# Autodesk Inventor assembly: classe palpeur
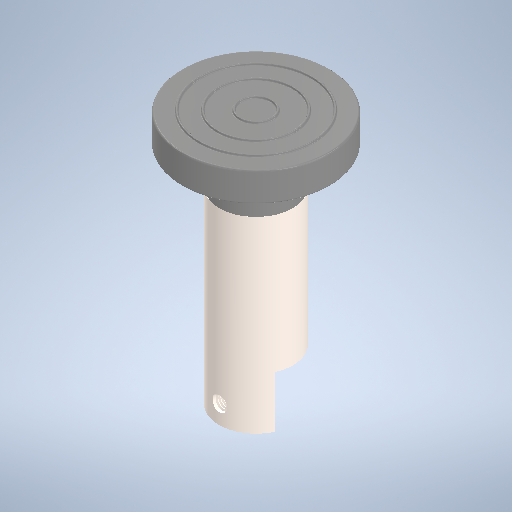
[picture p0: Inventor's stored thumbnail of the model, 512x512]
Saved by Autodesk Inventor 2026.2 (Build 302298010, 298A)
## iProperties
Created: 1601-01
Part Number: classe palpeur
Document SubType Name: Assembly
Designer: mel
Part Number: Appareil_de_massage
Sending System: SOLIDWORKS 2023
Last Saved Date: 2025-04-02
Author: mel
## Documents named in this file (3)
- C:\Users\mel\Downloads\18256-itec-20250709t050547z-1-001 (1)\ITEC\Ressources\ITEC00_SW_Appareil_de_massage\S1Appareil_de_massage\S1Appareil_de_massage\classe palpeur.iam
- C:\Users\mel\Downloads\18256-itec-20250709t050547z-1-001 (1)\ITEC\Ressources\ITEC00_SW_Appareil_de_massage\S1Appareil_de_massage\S1Appareil_de_massage\S1Piston.ipt
- C:\Users\mel\Downloads\18256-itec-20250709t050547z-1-001 (1)\ITEC\Ressources\ITEC00_SW_Appareil_de_massage\S1Appareil_de_massage\S1Appareil_de_massage\S1Tete_de_massage.ipt
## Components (2 placed, 2 different names)
1. Piston-1
2. Tete_de_massage-1
